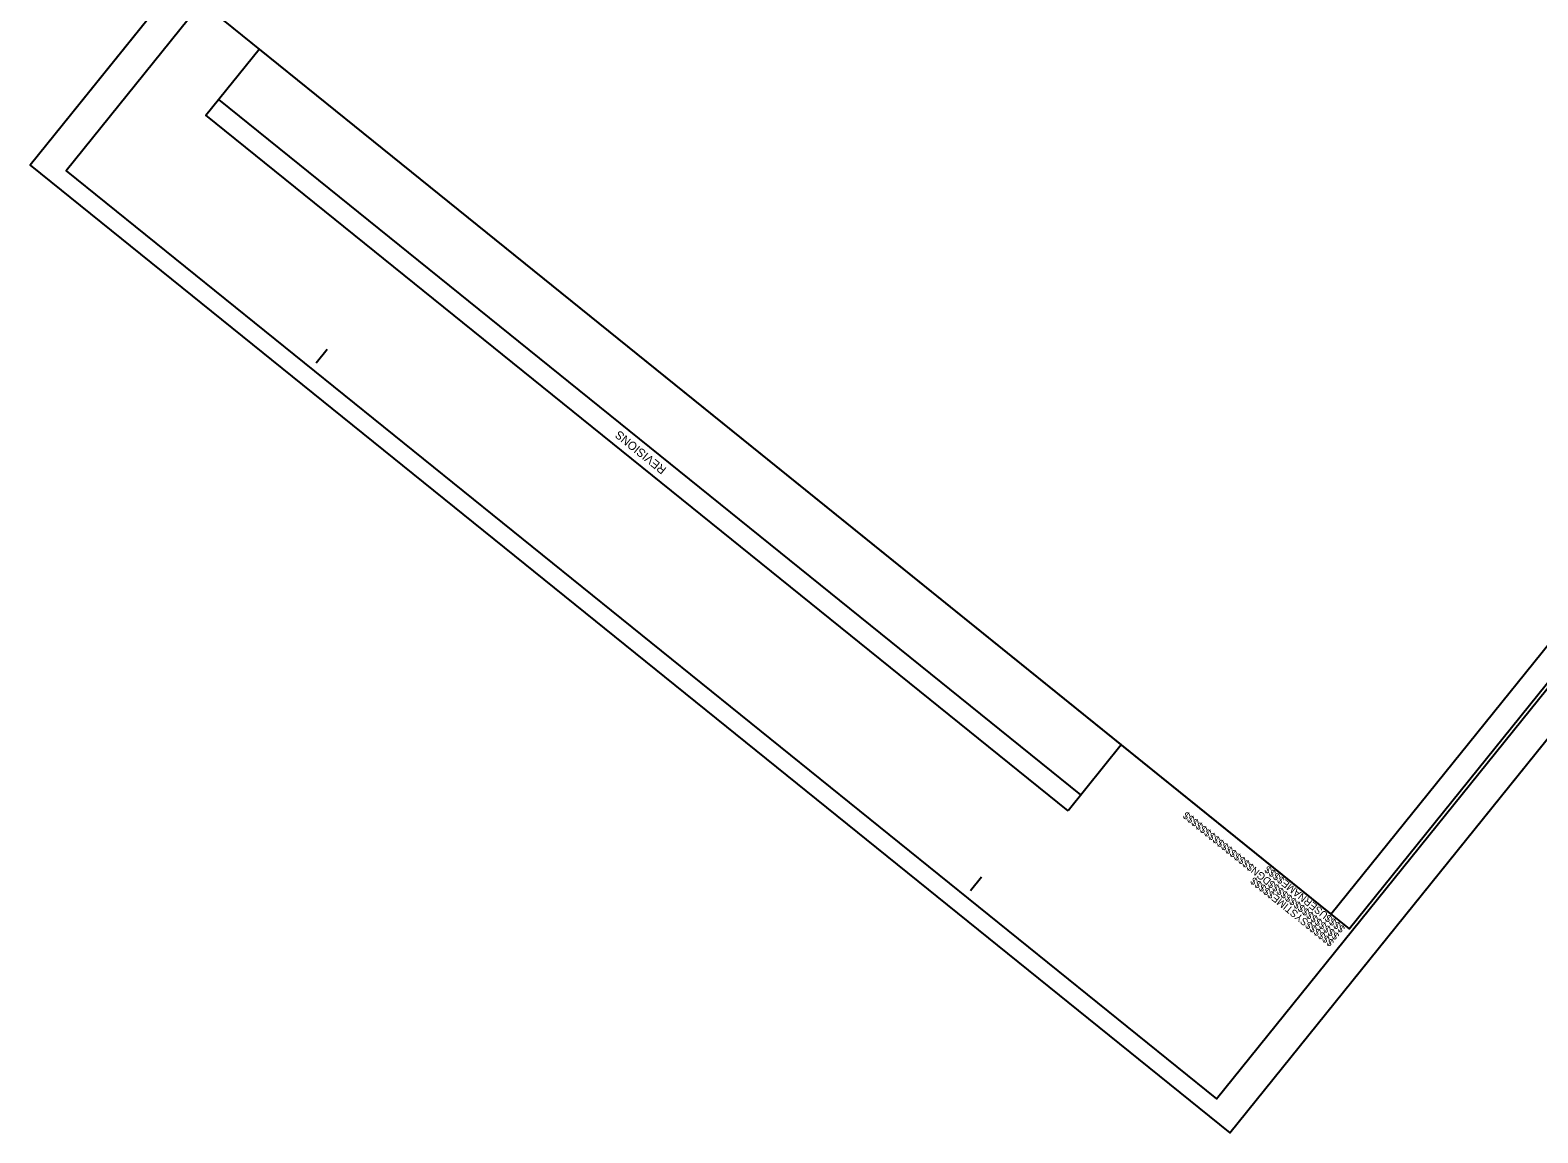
# Model space of a CAD drawing. Extents: x 1489015 to 1490928, y 499814 to 501978.
# Drawn here: x 1489015 to 1490091, y 499814 to 500601 of the extents above; entities that cross this region are included whole.
import ezdxf

# ---------------------------------------------------------------- set-up
doc = ezdxf.new("R2010")
doc.units = 0
for name, color, linetype in [('Sheet Block Revision CELL', 7, 'Continuous'), ('Sheet Clip Boundary CELL', 7, 'Continuous'), ('Sheet Cutting Line CELL', 7, 'Continuous'), ('Sheet Plot Border Inside CELL', 7, 'Continuous'), ('Sheet Plot Border Outside CELL', 7, 'Continuous'), ('Sheet Summary Earthwork CELL', 7, 'Continuous'), ('Sheet Typical CELL', 7, 'Continuous')]:
    doc.layers.add(name, color=color, linetype=linetype)

msp = doc.modelspace()

# ---------------------------------------------------------------- linework, layer by layer
at = {"layer": 'Sheet Block Revision CELL'}
msp.add_line((1489764.8, 500055.3), (1489149.4, 500551.6), dxfattribs=at)
msp.add_lwpolyline([(1489755.7, 500044), (1489140.2, 500540.3), (1489178.2, 500587.4), (1489793.7, 500091.1)], close=True, dxfattribs=at)
at = {"layer": 'Sheet Clip Boundary CELL'}
msp.add_lwpolyline([(1489943.4, 499970.3), (1490726.3, 500941), (1489921.9, 501589.7), (1489139.1, 500619)], close=True, dxfattribs=at)
at = {"layer": 'Sheet Cutting Line CELL'}
for p, q in [((1490072, 501815.5), (1489014.8, 500504.7)), ((1489871.1, 499814.2), (1490928.2, 501125)), ((1489014.8, 500504.7), (1489871.1, 499814.2))]:
    msp.add_line(p, q, dxfattribs=at)
at = {"layer": 'Sheet Plot Border Inside CELL'}
msp.add_lwpolyline([(1490086.6, 501797.9), (1489040.5, 500500.7), (1489861.8, 499838.4), (1490907.9, 501135.6)], close=True, dxfattribs=at)
at = {"layer": 'Sheet Plot Border Outside CELL'}
msp.add_lwpolyline([(1490072, 501815.5), (1489014.8, 500504.7), (1489871.1, 499814.2), (1490928.2, 501125)], close=True, dxfattribs=at)
at = {"layer": 'Sheet Summary Earthwork CELL'}
for p, q in [((1489219.1, 500363.7), (1489226.9, 500373.4)), ((1489686.1, 499987.1), (1489694, 499996.8)), ((1489956.5, 499959.8), (1489956.5, 499959.8)), ((1489956.5, 499959.8), (1489956.5, 499959.8)), ((1489956.5, 499959.8), (1489956.5, 499959.8)), ((1489956.5, 499959.8), (1489956.5, 499959.8)), ((1489956.5, 499959.8), (1489956.5, 499959.8)), ((1489956.5, 499959.8), (1489956.5, 499959.8)), ((1489956.5, 499959.8), (1489956.5, 499959.8)), ((1489956.5, 499959.8), (1489956.5, 499959.8)), ((1489956.5, 499959.8), (1489956.5, 499959.8)), ((1489956.5, 499959.8), (1489956.5, 499959.8)), ((1489956.5, 499959.8), (1489956.5, 499959.8)), ((1489956.5, 499959.8), (1489956.5, 499959.8)), ((1489956.5, 499959.8), (1489956.5, 499959.8)), ((1489956.5, 499959.8), (1489956.5, 499959.8)), ((1489956.5, 499959.8), (1489956.5, 499959.8)), ((1489956.5, 499959.8), (1489956.5, 499959.8)), ((1489956.5, 499959.8), (1489956.5, 499959.8)), ((1489956.5, 499959.8), (1489956.5, 499959.8))]:
    msp.add_line(p, q, dxfattribs=at)
msp.add_lwpolyline([(1490080.7, 501786.6), (1489139.1, 500619), (1489956.5, 499959.8), (1490898.1, 501127.5)], close=True, dxfattribs=at)
msp.add_lwpolyline([(1489980, 499989), (1489980, 499989)], dxfattribs=at)
msp.add_lwpolyline([(1489980, 499989), (1489980, 499989)], dxfattribs=at)
at = {"layer": 'Sheet Typical CELL'}
msp.add_line((1489956.5, 499959.8), (1489956.5, 499959.8), dxfattribs=at)
msp.add_line((1489956.5, 499959.8), (1489956.5, 499959.8), dxfattribs=at)
msp.add_line((1489956.5, 499959.8), (1489956.5, 499959.8), dxfattribs=at)
msp.add_line((1489956.5, 499959.8), (1489956.5, 499959.8), dxfattribs=at)
msp.add_line((1489956.5, 499959.8), (1489956.5, 499959.8), dxfattribs=at)
msp.add_line((1489956.5, 499959.8), (1489956.5, 499959.8), dxfattribs=at)

# ---------------------------------------------------------------- texts
at = {"layer": 'Sheet Block Revision CELL'}
msp.add_text('REVISIONS', height=6, rotation=141.1156, dxfattribs=at).set_placement((1489469.5, 500288.3))
at = {"layer": 'Sheet Summary Earthwork CELL'}
for s, p in [('$$$$$$$$$$$$$$$$DGN$$$$$$$$$$$$$$$$', (1489949.8, 499955.4)), ('$$$$USERNAME$$$$', (1489953.9, 499960.5)), ('$$$$$$SYSTIME$$$$$', (1489946, 499950.7))]:
    msp.add_text(s, height=5.25, rotation=141.1156, dxfattribs=at).set_placement(p)

doc.saveas('drawing.dxf')
